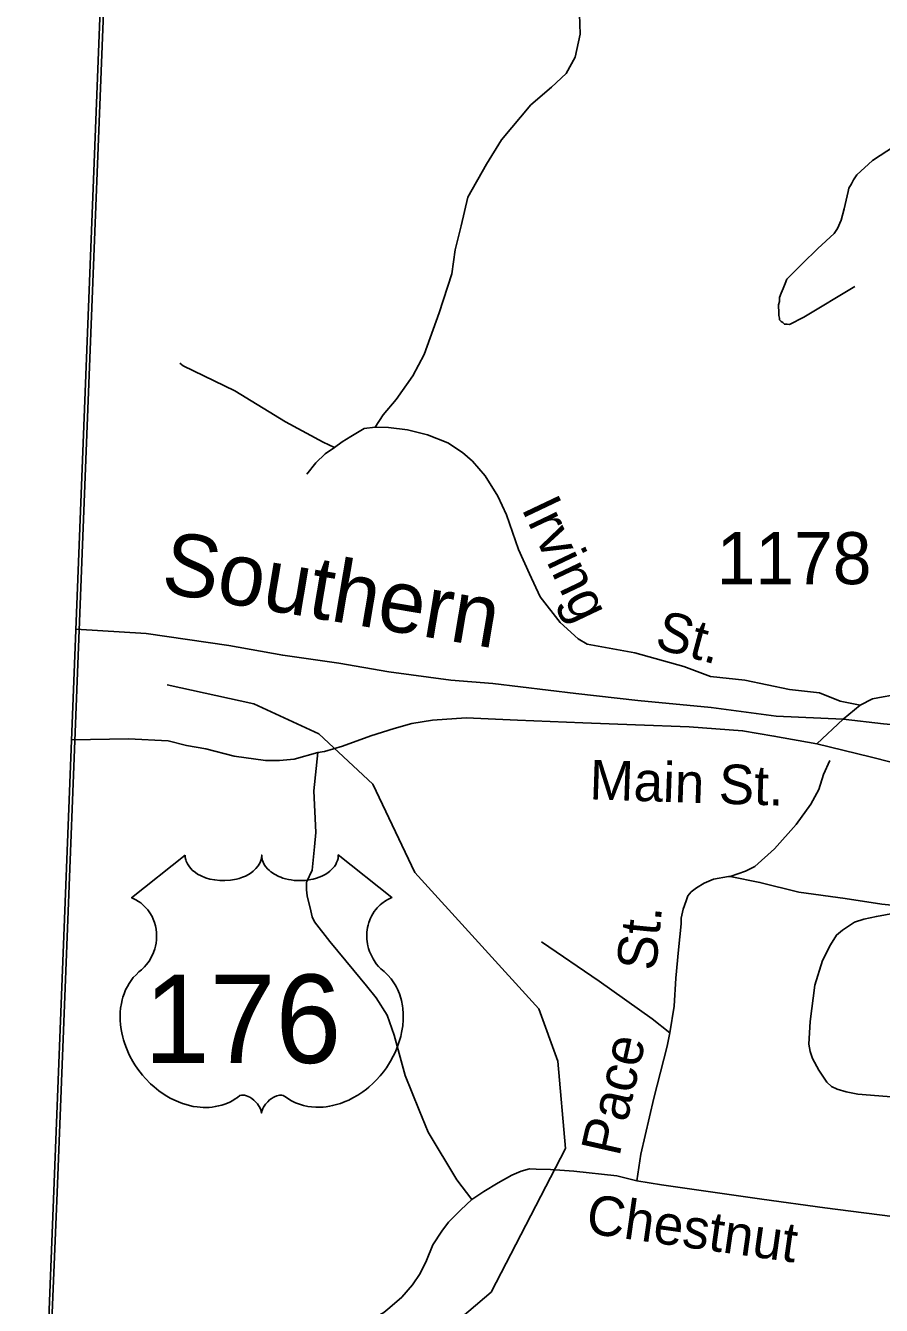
# Model space of a CAD drawing. Extents: x 990631 to 1056237, y 535999 to 585651.
# Drawn here: x 997020 to 999075, y 556457 to 559531 of the extents above; entities that cross this region are included whole.
import ezdxf

# ---------------------------------------------------------------- set-up
doc = ezdxf.new("R2010")
doc.units = 0
for name, color, linetype in [('Exist Boundary Political City Limit New', 7, 'Continuous'), ('Exist Boundary Political CountyLine', 7, 'Continuous'), ('Exist Hydrographic Creek Single Shore', 7, 'Continuous'), ('Exist Railroad Mainline', 7, 'Continuous'), ('Exist Railroad Mainline Label', 7, 'Continuous'), ('Exist Road Non-System Type 51', 7, 'Continuous'), ('Exist Road Non-System Type 51 Label', 7, 'Continuous'), ('Exist Road Primary US Attributed', 7, 'Continuous'), ('Exist Road Primary US Label', 7, 'Continuous'), ('Exist Road Primary US Shield CELL', 7, 'Continuous'), ('Exist Road Primary US Shield Number Label', 7, 'Continuous'), ('Exist Road Secondary Type 51 Attributed', 7, 'Continuous'), ('Exist Road Secondary Type 51 Number Label', 7, 'Continuous')]:
    doc.layers.add(name, color=color, linetype=linetype)

msp = doc.modelspace()

# ---------------------------------------------------------------- linework, layer by layer
at = {"layer": 'Exist Boundary Political City Limit New'}
msp.add_lwpolyline([(997287.3, 562212.8), (997193.9, 561589.8), (997116.1, 561508), (997182.2, 561453.4), (997213.4, 561410.6), (997240.6, 561391.1), (997271.8, 561371.7), (997473.4, 560867.4), (997258.8, 560880.4), (997248.1, 560565.8), (997215.4, 559766.4), (997165.4, 558509.2), (997096.1, 556728.4), (997064.9, 555976.8), (997032.1, 554993.6), (997976.4, 554966.1)], dxfattribs=at)
at = {"layer": 'Exist Boundary Political CountyLine'}
for points in [[(998707, 546620.1), (998768.4, 547288.4), (998835.1, 547966.7), (998916.8, 548792.5), (998991.2, 549584.6), (999111.7, 550801.4), (999167.8, 551397.9), (999229.7, 552060.2), (999297, 552754.5), (999373.1, 553532.6), (999431, 554135), (999500.6, 554839.1), (999504.7, 554901), (997102.8, 554995.1), (997020.3, 554998), (997026.3, 555160.3), (997250.5, 560876.2), (1000082.8, 560713.6), (1000385.5, 563731), (1000441.4, 564287.1), (1000460.4, 564476.5), (1000472.3, 564594.7), (1000608.5, 565973.2)], [(998637.8, 545891.8), (998696.2, 546502.4), (998768.4, 547288.4), (998835.1, 547966.7), (998916.8, 548792.5), (998991.2, 549584.6), (999111.7, 550801.4), (999167.8, 551397.9), (999229.7, 552060.2), (999297, 552754.5), (999373.1, 553532.6), (999431, 554135), (999500.6, 554839.1), (999504.7, 554901), (997102.8, 554995.1), (997020.3, 554998), (997026.3, 555160.3), (997250.5, 560876.2), (1000082.8, 560713.6), (1000385.5, 563731), (1000441.4, 564287.1), (1000460.4, 564476.5), (1000472.3, 564594.7), (1000608.5, 565973.2)]]:
    msp.add_lwpolyline(points, dxfattribs=at)
at = {"layer": 'Exist Hydrographic Creek Single Shore'}
msp.add_lwpolyline([(997567.5, 556116.7), (997924, 556306.5), (998138.5, 556489.2), (998316.9, 556833.5), (998298.7, 557043.9), (998252.9, 557169.5), (997955.4, 557497.1), (997854, 557709.2), (997724.7, 557830), (997568.6, 557902.1), (997360.5, 557947.5)], dxfattribs=at)
msp.add_lwpolyline([(997567.5, 556116.7), (997924, 556306.5), (998138.5, 556489.2), (998316.9, 556833.5), (998298.7, 557043.9), (998252.9, 557169.5), (997955.4, 557497.1), (997854, 557709.2), (997724.7, 557830), (997568.6, 557902.1), (997360.5, 557947.5)], dxfattribs=at)
at = {"layer": 'Exist Railroad Mainline'}
msp.add_lwpolyline([(997140.9, 558081), (997310, 558071.1), (997508, 558042.4), (997637.8, 558018.6), (997772.5, 557999.8), (997892.8, 557978.5), (998041.3, 557958.6), (998142.7, 557950.4), (998341.9, 557926.4), (998490.9, 557910.1), (998666.3, 557893.3), (998823, 557872), (998983.6, 557865), (999080.3, 557853.5), (999344.9, 557828.8), (999517.6, 557813.4), (999629.8, 557799.5), (999880.8, 557775.2)], dxfattribs=at)
at = {"layer": 'Exist Road Non-System Type 51'}
for points in [[(998349.9, 559582.8), (998351.7, 559510.6), (998339.8, 559455), (998318.4, 559415.6), (998283.3, 559382.9), (998233.8, 559340.5), (998163.1, 559256.7), (998127.1, 559198), (998082.3, 559119.3), (998066.1, 559049.8), (998052.2, 558992.2), (998044.2, 558934.6), (998013.1, 558841.4), (997977.7, 558740.7), (997950, 558689.4), (997910.1, 558632.8), (997878.7, 558595.8), (997859.9, 558566.4)], [(999107.1, 559241.2), (999054, 559207.1), (999016.7, 559172.2), (999008.4, 559160.6), (999004, 559150.7), (998997.6, 559140.8), (998995.5, 559132.9), (998986, 559091.2), (998979, 559063.4), (998970.4, 559043.7), (998962, 559031.9), (998922.9, 558995.3), (998885.5, 558958.4), (998848.4, 558921.8), (998844, 558911.8), (998839.5, 558899.9), (998835.1, 558888), (998830.9, 558878.3), (998830.5, 558868.3), (998828.3, 558860.3), (998829.5, 558840.3), (998829.4, 558834.3), (998831.1, 558828.3), (998831, 558824.3), (998834.9, 558820), (998838.9, 558817.9), (998842.6, 558813.8), (998848.8, 558813.5), (998854.8, 558813.4), (998889.3, 558830.3), (999011.8, 558904.3)], [(997762.1, 558517.5), (997734.6, 558530.5), (997644.1, 558579.5), (997522.6, 558653.6), (997398.4, 558714), (997390.6, 558720.4)], [(997859.9, 558566.4), (997833.6, 558563.3), (997801.1, 558544.4), (997780.6, 558531), (997762.1, 558517.5)], [(999024.4, 557899.1), (998976.6, 557908.6), (998926.6, 557928.5), (998854.5, 557936.5), (998747.3, 557958.5), (998665.1, 557967.6), (998601, 557991.6), (998483.7, 558024.7), (998368.7, 558045.2), (998347.2, 558057.8), (998304.4, 558097.3), (998256.4, 558158.9), (998230.3, 558213.8), (998204.3, 558272.7), (998175, 558355.8), (998154.4, 558400.4), (998124, 558449.4), (998093.3, 558484.7), (998069.9, 558505.3), (998034.6, 558528.5), (997985.2, 558548.3), (997937.6, 558559.8), (997891.7, 558565.3), (997859.9, 558566.4)], [(997762.1, 558517.5), (997739.6, 558502.4), (997717, 558481), (997696, 558453.9)], [(997721.9, 557784.8), (997712.7, 557692.7), (997717.2, 557592.6), (997714.2, 557558.6), (997708.2, 557502.7), (997695.2, 557473.2), (997695.1, 557465.2), (997694.7, 557455.2), (997696.2, 557441.1), (997705.1, 557404.7), (997708.6, 557390.7), (997714.1, 557378.5), (997750.6, 557331.2), (997808.2, 557261.2), (997839, 557224.2), (997862.1, 557195.5), (997888.9, 557154.5), (997905.1, 557105.8), (997931.9, 557009), (997965.3, 556925.7), (997987.4, 556873.1), (998055.7, 556758.6), (998092.2, 556711.5)], [(998712.4, 557487.2), (998748.9, 557500.1), (998771.3, 557511.3), (998818.8, 557553.7), (998870.6, 557612.1), (998906.4, 557661), (998925.5, 557696.2), (998936.6, 557732), (998951.9, 557765.5)], [(998567.8, 557111.8), (998577.9, 557175.4), (998582.2, 557243.4), (998588.4, 557311.3), (998594.5, 557373.2), (998594.9, 557387.2), (998599.6, 557408.9), (998606.4, 557428.8), (998610.8, 557440.7), (998619, 557450.3), (998631.4, 557459.9), (998649.9, 557471.3), (998672.1, 557480.6), (998708.4, 557487.3), (998712.4, 557487.2)], [(999190.2, 557409.2), (999076.4, 557421.1), (998988.8, 557434), (998877.3, 557449.7), (998783.9, 557472.8), (998712.4, 557487.2)], [(999270.6, 556944.2), (999019.2, 556964.7), (998991.2, 556969.6), (998969.6, 556976.3), (998955.7, 556982.8), (998944.1, 556993.2), (998925.1, 557021.8), (998909.8, 557050.3), (998904.6, 557066.6), (998901.1, 557084.7), (998904.8, 557138.6), (998915.8, 557226.2), (998933.8, 557285.7), (998953.2, 557323.1), (998967.8, 557346.6), (998982.3, 557358.1), (999010.9, 557377.2), (999033.2, 557384.5), (999063.4, 557391.5), (999119.8, 557401.6)], [(998258.9, 557330.3), (998397.8, 557235.5), (998524.9, 557145.3), (998567.8, 557111.8)], [(998487.8, 556756.1), (998498.1, 556819.9), (998528.6, 556955), (998560.7, 557080), (998567.8, 557111.8)], [(998487.8, 556756.1), (998440.2, 556767.9), (998336.6, 556779.4), (998280.7, 556783.1), (998246.7, 556784.2), (998230.7, 556784.9), (998210.4, 556779.5), (998188.2, 556770.2), (998155.4, 556751.2), (998120.8, 556730.5), (998092.2, 556711.5)], [(999520, 556623.7), (999484.3, 556629), (999428.8, 556644.7), (999353, 556657.2), (999257.1, 556660.6), (999133.4, 556666.7), (998940, 556691.2), (998788.6, 556712.2), (998547.6, 556746.3), (998487.8, 556756.1)], [(998092.2, 556711.5), (998065.3, 556686.2), (998036.3, 556657.2), (998019.6, 556635.7), (997998.4, 556602.6), (997983.2, 556564.8), (997968.2, 556533.3), (997949.2, 556506.1), (997924.2, 556476.8), (997895.3, 556451.8), (997880.9, 556440.3), (997831.9, 556411.9), (997779.2, 556389.7), (997734.7, 556375.2), (997698.2, 556362.3), (997662.1, 556357.5), (997621.9, 556354.9), (997574.3, 556366.4), (997484.9, 556387.4), (997395.7, 556410.5), (997365.8, 556413.5)]]:
    msp.add_lwpolyline(points, dxfattribs=at)
at = {"layer": 'Exist Road Primary US Attributed'}
for points in [[(997130.5, 557815.7), (997267.4, 557817.5), (997362.9, 557813), (997406.5, 557802.1), (997453.1, 557794.2), (997521.4, 557776.3), (997596.2, 557765.9), (997629.8, 557765.9), (997665.5, 557768.9), (997721.9, 557784.8), (997737.8, 557787.7), (997781.4, 557800.6), (997849.2, 557824.9), (997905.7, 557842.7), (997948.2, 557854.6), (997997.5, 557863.1), (998078.7, 557868), (998201.3, 557863), (998358.7, 557856.1), (998485, 557851.6), (998613.7, 557846.7), (998742, 557837.3), (998817.3, 557824.4), (998920.3, 557805.6)], [(998920.3, 557805.6), (999048.5, 557774.4), (999272.3, 557717.9), (999415.4, 557679.8), (999540.7, 557645.5), (999606.6, 557633.2), (999648.2, 557631.2), (999671.8, 557633.3), (999704.2, 557644.3), (999721.4, 557655), (999733.1, 557660.6), (999751.6, 557671.8), (999778.9, 557693.6)]]:
    msp.add_lwpolyline(points, dxfattribs=at)
at = {"layer": 'Exist Road Primary US Shield CELL'}
msp.add_lwpolyline([(997403.3, 557538.6), (997403.6, 557533.2), (997404.9, 557526.9), (997405.9, 557523.7), (997408.8, 557517.4), (997413.7, 557510.1), (997420.5, 557502.8), (997428.2, 557496.5), (997433.3, 557493.2), (997442.1, 557488.5), (997452, 557484.3), (997463.1, 557481.1), (997474.5, 557478.8), (997486.8, 557477.5), (997499.1, 557477.2), (997512.3, 557478.2), (997526.9, 557481), (997533.6, 557482.8), (997541.1, 557485.4), (997548.1, 557488.3), (997555.8, 557492.4), (997561.9, 557496.3), (997566.8, 557499.8), (997573.6, 557506.3), (997579, 557513.1), (997581.3, 557516.9), (997583.3, 557520.6), (997586, 557528.3), (997586.7, 557531.7), (997587.3, 557538.8), (997587.7, 557532.9), (997588.3, 557529.1), (997589.3, 557525.5), (997590.8, 557521.6), (997593.6, 557516.1), (997596.6, 557511.6), (997602.3, 557504.8), (997605.9, 557501.5), (997609.2, 557498.8), (997617.9, 557492.8), (997628.1, 557487.6), (997633.1, 557485.4), (997638.3, 557483.6), (997644.8, 557481.6), (997651.6, 557480.1), (997658.3, 557478.9), (997665.1, 557477.9), (997672.1, 557477.4), (997677.8, 557477.2), (997684.8, 557477.3), (997691.2, 557477.7), (997697.9, 557478.5), (997705.1, 557479.7), (997711, 557481), (997718.7, 557483), (997725.7, 557485.5), (997731.9, 557488.2), (997739.9, 557492.4), (997746.3, 557496.4), (997751, 557500.2), (997756.6, 557505.4), (997762, 557511.5), (997765.1, 557516), (997767.3, 557520.6), (997769.3, 557525.5), (997770.6, 557530.7), (997771.2, 557535.1), (997771.3, 557539), (997899.9, 557436.5), (997896.9, 557435.4), (997889.9, 557432), (997884.3, 557428.7), (997875.5, 557422.5), (997871.7, 557419), (997867.9, 557415.5), (997864.4, 557411.7), (997861.3, 557408.1), (997857.6, 557402.9), (997854.3, 557397.8), (997851, 557392.1), (997848.6, 557387.1), (997844.7, 557376.8), (997842.8, 557370.2), (997841.5, 557364.7), (997840, 557353.2), (997839.6, 557347.8), (997839.6, 557342.4), (997840, 557336.7), (997840.5, 557331.2), (997841.5, 557325.5), (997842.4, 557320.5), (997844, 557314.3), (997846.3, 557307.2), (997849.1, 557300.3), (997854.9, 557289.1), (997862.5, 557277.7), (997867.9, 557271.3), (997873.2, 557265.8), (997881.2, 557259.2), (997885.4, 557255.4), (997890.4, 557250.4), (997898.4, 557241.1), (997901.7, 557236.7), (997905, 557231.7), (997908, 557226.6), (997911.1, 557221.2), (997913.5, 557216.4), (997918, 557205.4), (997921.3, 557194.6), (997922.8, 557189), (997925.2, 557176.4), (997926.2, 557170.2), (997927.1, 557157.9), (997927.2, 557143), (997926, 557128.8), (997923.4, 557112.3), (997921.2, 557102.5), (997917.8, 557091), (997914.5, 557081), (997908.6, 557066.4), (997903.4, 557055.7), (997896.7, 557043.3), (997892.1, 557035.8), (997886.7, 557027.7), (997879.9, 557018.4), (997872, 557008.6), (997862.5, 556998.1), (997854.8, 556990.5), (997844.8, 556981.5), (997838.7, 556976.5), (997830.1, 556969.9), (997818.2, 556962), (997806.5, 556955.3), (997796.6, 556950.2), (997787.8, 556946.4), (997776.4, 556942.1), (997757.4, 556936.8), (997750.5, 556935.4), (997742.3, 556934.2), (997734.6, 556933.4), (997727.2, 556932.9), (997717.1, 556932.9), (997707.2, 556933.7), (997697.8, 556935.1), (997688, 556937.1), (997677.7, 556940.2), (997668.4, 556943.8), (997659, 556948.4), (997643.1, 556958.5), (997638.5, 556960.9), (997635.9, 556961.6), (997629.8, 556961.9), (997624, 556960.7), (997618.1, 556958.3), (997614.5, 556956.4), (997609.8, 556953.3), (997606.1, 556950.4), (997601.7, 556946.2), (997598.7, 556942.7), (997596.4, 556940), (997591.9, 556932.9), (997590.3, 556929.6), (997588.6, 556925.3), (997587.1, 556918.9), (997585.1, 556926.9), (997582.8, 556932.3), (997580, 556936.8), (997577.2, 556940.8), (997572.7, 556946), (997568.7, 556949.9), (997563.8, 556953.8), (997558.6, 556957), (997554.5, 556959.1), (997550.7, 556960.5), (997546.1, 556961.7), (997542.3, 556962), (997539.2, 556961.9), (997534.9, 556960.9), (997529.1, 556956.7), (997523.6, 556952.9), (997517.6, 556949.2), (997510.4, 556945.4), (997505.2, 556943), (997498.9, 556940.5), (997491.7, 556938.1), (997483.8, 556936.1), (997475.6, 556934.5), (997468.5, 556933.3), (997460.8, 556932.6), (997453.9, 556932.4), (997446.7, 556932.5), (997439.9, 556933), (997432.1, 556933.7), (997422.4, 556935.1), (997414.3, 556937), (997405.8, 556939.3), (997397.1, 556942), (997387.8, 556945.6), (997376.1, 556950.6), (997367.9, 556954.8), (997355.1, 556962.2), (997340.1, 556972.6), (997328.7, 556981.8), (997320.4, 556989.3), (997308.2, 557001.8), (997301, 557009.9), (997289.7, 557024.5), (997282.5, 557035.1), (997277.8, 557042.8), (997271, 557055.3), (997267.2, 557063.1), (997262.4, 557074.5), (997258.5, 557084.9), (997255.4, 557094.8), (997253.6, 557101.1), (997251.2, 557112.1), (997249.7, 557119.9), (997248.3, 557130.7), (997247.5, 557142), (997247.3, 557152.4), (997247.6, 557161.1), (997248.6, 557171.2), (997250.3, 557181.9), (997252.4, 557191.1), (997254.2, 557197.7), (997256.9, 557205.7), (997260.6, 557214.6), (997264.8, 557223.1), (997268.9, 557230.2), (997274, 557237.8), (997279, 557244.3), (997285.5, 557251.4), (997292.4, 557257.9), (997298.6, 557263), (997306.1, 557270.3), (997310, 557274.7), (997314.6, 557280.9), (997318.4, 557286.6), (997321.3, 557291.7), (997325.2, 557299.2), (997327.6, 557304.8), (997330.5, 557313.5), (997332, 557319.6), (997333.5, 557327.4), (997334.5, 557334.8), (997334.9, 557344), (997334.7, 557351.6), (997333.7, 557360.4), (997332, 557369), (997330, 557376.4), (997326.8, 557384.9), (997323.9, 557391.1), (997319, 557399.6), (997313.5, 557407.4), (997307.8, 557413.8), (997302.1, 557419.5), (997296.7, 557423.7), (997291.5, 557427.5), (997284.9, 557431.4), (997278.6, 557434.5), (997274.7, 557436.1)], close=True, dxfattribs=at)
msp.add_lwpolyline([(997403.3, 557538.6), (997403.6, 557533.2), (997404.9, 557526.9), (997405.9, 557523.7), (997408.8, 557517.4), (997413.7, 557510.1), (997420.5, 557502.8), (997428.2, 557496.5), (997433.3, 557493.2), (997442.1, 557488.5), (997452, 557484.3), (997463.1, 557481.1), (997474.5, 557478.8), (997486.8, 557477.5), (997499.1, 557477.2), (997512.3, 557478.2), (997526.9, 557481), (997533.6, 557482.8), (997541.1, 557485.4), (997548.1, 557488.3), (997555.8, 557492.4), (997561.9, 557496.3), (997566.8, 557499.8), (997573.6, 557506.3), (997579, 557513.1), (997581.3, 557516.9), (997583.3, 557520.6), (997586, 557528.3), (997586.7, 557531.7), (997587.3, 557538.8), (997587.7, 557532.9), (997588.3, 557529.1), (997589.3, 557525.5), (997590.8, 557521.6), (997593.6, 557516.1), (997596.6, 557511.6), (997602.3, 557504.8), (997605.9, 557501.5), (997609.2, 557498.8), (997617.9, 557492.8), (997628.1, 557487.6), (997633.1, 557485.4), (997638.3, 557483.6), (997644.8, 557481.6), (997651.6, 557480.1), (997658.3, 557478.9), (997665.1, 557477.9), (997672.1, 557477.4), (997677.8, 557477.2), (997684.8, 557477.3), (997691.2, 557477.7), (997697.9, 557478.5), (997705.1, 557479.7), (997711, 557481), (997718.7, 557483), (997725.7, 557485.5), (997731.9, 557488.2), (997739.9, 557492.4), (997746.3, 557496.4), (997751, 557500.2), (997756.6, 557505.4), (997762, 557511.5), (997765.1, 557516), (997767.3, 557520.6), (997769.3, 557525.5), (997770.6, 557530.7), (997771.2, 557535.1), (997771.3, 557539), (997899.9, 557436.5), (997896.9, 557435.4), (997889.9, 557432), (997884.3, 557428.7), (997875.5, 557422.5), (997871.7, 557419), (997867.9, 557415.5), (997864.4, 557411.7), (997861.3, 557408.1), (997857.6, 557402.9), (997854.3, 557397.8), (997851, 557392.1), (997848.6, 557387.1), (997844.7, 557376.8), (997842.8, 557370.2), (997841.5, 557364.7), (997840, 557353.2), (997839.6, 557347.8), (997839.6, 557342.4), (997840, 557336.7), (997840.5, 557331.2), (997841.5, 557325.5), (997842.4, 557320.5), (997844, 557314.3), (997846.3, 557307.2), (997849.1, 557300.3), (997854.9, 557289.1), (997862.5, 557277.7), (997867.9, 557271.3), (997873.2, 557265.8), (997881.2, 557259.2), (997885.4, 557255.4), (997890.4, 557250.4), (997898.4, 557241.1), (997901.7, 557236.7), (997905, 557231.7), (997908, 557226.6), (997911.1, 557221.2), (997913.5, 557216.4), (997918, 557205.4), (997921.3, 557194.6), (997922.8, 557189), (997925.2, 557176.4), (997926.2, 557170.2), (997927.1, 557157.9), (997927.2, 557143), (997926, 557128.8), (997923.4, 557112.3), (997921.2, 557102.5), (997917.8, 557091), (997914.5, 557081), (997908.6, 557066.4), (997903.4, 557055.7), (997896.7, 557043.3), (997892.1, 557035.8), (997886.7, 557027.7), (997879.9, 557018.4), (997872, 557008.6), (997862.5, 556998.1), (997854.8, 556990.5), (997844.8, 556981.5), (997838.7, 556976.5), (997830.1, 556969.9), (997818.2, 556962), (997806.5, 556955.3), (997796.6, 556950.2), (997787.8, 556946.4), (997776.4, 556942.1), (997757.4, 556936.8), (997750.5, 556935.4), (997742.3, 556934.2), (997734.6, 556933.4), (997727.2, 556932.9), (997717.1, 556932.9), (997707.2, 556933.7), (997697.8, 556935.1), (997688, 556937.1), (997677.7, 556940.2), (997668.4, 556943.8), (997659, 556948.4), (997643.1, 556958.5), (997638.5, 556960.9), (997635.9, 556961.6), (997629.8, 556961.9), (997624, 556960.7), (997618.1, 556958.3), (997614.5, 556956.4), (997609.8, 556953.3), (997606.1, 556950.4), (997601.7, 556946.2), (997598.7, 556942.7), (997596.4, 556940), (997591.9, 556932.9), (997590.3, 556929.6), (997588.6, 556925.3), (997587.1, 556918.9), (997585.1, 556926.9), (997582.8, 556932.3), (997580, 556936.8), (997577.2, 556940.8), (997572.7, 556946), (997568.7, 556949.9), (997563.8, 556953.8), (997558.6, 556957), (997554.5, 556959.1), (997550.7, 556960.5), (997546.1, 556961.7), (997542.3, 556962), (997539.2, 556961.9), (997534.9, 556960.9), (997529.1, 556956.7), (997523.6, 556952.9), (997517.6, 556949.2), (997510.4, 556945.4), (997505.2, 556943), (997498.9, 556940.5), (997491.7, 556938.1), (997483.8, 556936.1), (997475.6, 556934.5), (997468.5, 556933.3), (997460.8, 556932.6), (997453.9, 556932.4), (997446.7, 556932.5), (997439.9, 556933), (997432.1, 556933.7), (997422.4, 556935.1), (997414.3, 556937), (997405.8, 556939.3), (997397.1, 556942), (997387.8, 556945.6), (997376.1, 556950.6), (997367.9, 556954.8), (997355.1, 556962.2), (997340.1, 556972.6), (997328.7, 556981.8), (997320.4, 556989.3), (997308.2, 557001.8), (997301, 557009.9), (997289.7, 557024.5), (997282.5, 557035.1), (997277.8, 557042.8), (997271, 557055.3), (997267.2, 557063.1), (997262.4, 557074.5), (997258.5, 557084.9), (997255.4, 557094.8), (997253.6, 557101.1), (997251.2, 557112.1), (997249.7, 557119.9), (997248.3, 557130.7), (997247.5, 557142), (997247.3, 557152.4), (997247.6, 557161.1), (997248.6, 557171.2), (997250.3, 557181.9), (997252.4, 557191.1), (997254.2, 557197.7), (997256.9, 557205.7), (997260.6, 557214.6), (997264.8, 557223.1), (997268.9, 557230.2), (997274, 557237.8), (997279, 557244.3), (997285.5, 557251.4), (997292.4, 557257.9), (997298.6, 557263), (997306.1, 557270.3), (997310, 557274.7), (997314.6, 557280.9), (997318.4, 557286.6), (997321.3, 557291.7), (997325.2, 557299.2), (997327.6, 557304.8), (997330.5, 557313.5), (997332, 557319.6), (997333.5, 557327.4), (997334.5, 557334.8), (997334.9, 557344), (997334.7, 557351.6), (997333.7, 557360.4), (997332, 557369), (997330, 557376.4), (997326.8, 557384.9), (997323.9, 557391.1), (997319, 557399.6), (997313.5, 557407.4), (997307.8, 557413.8), (997302.1, 557419.5), (997296.7, 557423.7), (997291.5, 557427.5), (997284.9, 557431.4), (997278.6, 557434.5), (997274.7, 557436.1)], close=True, dxfattribs=at)
at = {"layer": 'Exist Road Secondary Type 51 Attributed'}
msp.add_lwpolyline([(998920.3, 557805.6), (998983.6, 557865), (999024.4, 557899.1), (999053.9, 557913.6), (999079.7, 557918.5), (999116.3, 557925.5), (999157.9, 557922.5), (999246.1, 557906.6), (999327.3, 557898.7), (999408.5, 557896.7), (999558.5, 557884.1), (999707.7, 557865.9), (999822.6, 557843.8), (999942.2, 557821.8)], dxfattribs=at)

# ---------------------------------------------------------------- texts
at = {"layer": 'Exist Railroad Mainline Label'}
msp.add_text('Southern', height=150, rotation=350.412, dxfattribs=at).set_placement((997342.2, 558170.6))
msp.add_text('Southern', height=150, rotation=350.412, dxfattribs=at).set_placement((997342.2, 558170.6))
at = {"layer": 'Exist Road Non-System Type 51 Label'}
for s, rotation, p in [('Irving', 295.4089, (998209.9, 558371.5)), ('Irving', 295.4089, (998209.9, 558371.5)), ('St.', 344.9265, (998528.1, 558036.6)), ('St.', 344.9265, (998528.1, 558036.6)), ('St.', 84.4177, (998533.9, 557258.9)), ('St.', 84.4177, (998533.9, 557258.9)), ('Pace ', 77.2593, (998445.9, 556812.3)), ('Pace ', 77.2593, (998445.9, 556812.3)), ('Chestnut', 351.952, (998363.2, 556631)), ('Chestnut', 351.952, (998363.2, 556631))]:
    msp.add_text(s, height=95, rotation=rotation, dxfattribs=at).set_placement(p)
at = {"layer": 'Exist Road Primary US Label'}
msp.add_text('Main St.', height=95, rotation=358.1071, dxfattribs=at).set_placement((998373.5, 557672.6))
msp.add_text('Main St.', height=95, rotation=358.1071, dxfattribs=at).set_placement((998373.5, 557672.6))
at = {"layer": 'Exist Road Primary US Shield Number Label'}
msp.add_text('176', height=212.5, dxfattribs=at).set_placement((997304.4, 557039.3))
msp.add_text('176', height=212.5, dxfattribs=at).set_placement((997304.4, 557039.3))
at = {"layer": 'Exist Road Secondary Type 51 Number Label'}
msp.add_text('1178', height=125, dxfattribs=at).set_placement((998679.8, 558189.3))

doc.saveas('drawing.dxf')
